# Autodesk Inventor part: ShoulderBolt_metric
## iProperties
Company: Cooper Bussmann Denmark
Author: Peter Damgaard
Shininess: 60.0
PropertySet Name: _Private Model Information
Created: 2001-02
Part Number: ShoulderBolt_metric
Document SubType Name: Modeling
Designer: Peter Damgaard
Material: Steel, High Strength Low Alloy
Control State: 0
Master: False
Checked Out: False
PropertySet Name: Design Tracking Control
Density: 7.84
Volumn: 1.0724371659246204
Area: 8.535162991116971
PropertySet Name: Model Information
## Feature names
1. Shoulder [Revolution]
2. Shoulder_neck [Extrusion]
3. Head [Extrusion]
4. Thread_neck [Extrusion]
5. Thread_shoulder [Extrusion]
6. Hex [Extrusion]
7. Chamfer1
8. Fillet1
9. Chamfer2
10. Chamfer3
11. Fillet2
12. Chamfer7
